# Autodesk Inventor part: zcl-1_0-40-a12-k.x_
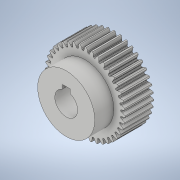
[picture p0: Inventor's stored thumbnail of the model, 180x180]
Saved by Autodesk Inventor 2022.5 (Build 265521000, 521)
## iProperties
Created: 2021-08
Part Number: zcl-1_0-40-a12-k.x_
Material: 一般
Document SubType Name: Modeling
Designer: ImaoCorp
Density: 1 g/cm^3
Appearance: 既定
Sending System: SOLIDWORKS 2019-2019304
MC: AMD64
MC_MODEL: Intel64 Family 6 Model 60 Stepping 3, GenuineIntel
OS: Windows_NT
FRU: Parasolid Version 31.0, build 290,  9- 1-2019
FORMAT: text
GUISE: transmit
KEY: zcl-1_0-40-a12-k
FILE: zcl-1_0-40-a12-k.x_t
DATE: Wed Aug 11 14:57:51 2021
Author: ImaoCorp
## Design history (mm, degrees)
feature "Base1"
node "ソリッド1"
